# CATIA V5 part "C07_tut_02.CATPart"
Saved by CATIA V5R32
Part number: Part1
Bounding box of the stored display mesh (mm): x 0 to 32, y -32 to 32, z -15 to 36
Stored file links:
  D:\PROJECTS\Project 2022\CATIA V5 6R 2022\Resources\Tutorial Files\c07_catia_v5_6r2022_tut\C07_tut_02.CATPart
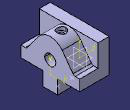
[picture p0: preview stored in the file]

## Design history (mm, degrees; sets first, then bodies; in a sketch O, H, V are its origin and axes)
Body1 (main body)
  Sketch1 on zx-plane, origin (0, 0, 0), H (-1, 0, 0), V (0, 0, 1)
    point P1 (0, 36)
    line L1 (0, 36) -> (0, 0)
    line L2 (0, 0) -> (-32, 0)
    line L3 (0, 36) -> (-12, 36)
    line L4 (-12, 36) -> (-12, 12)
    line L5 (-12, 12) -> (-32, 12)
    line L6 (-32, 12) -> (-32, 0)
    length L2 = 32
    length L3 = 12
    length L6 = 12
    distance L3 L2 = 36
    coincidence: P1 V
    vertical: L1 V, L4 V, L6 V
    horizontal: L2 H, L3 H, L5 H
  Pad1: profile Sketch1, direction (0, 1, 0), length 32, mirrored extent
  Sketch2 on face of Pad1 from Sketch1.L6, origin (32, 0, 0), H (0, 1, 0), V (0, 0, 1)
    arc A1 centre (0, 20) radius 16 from (12.9443, 29.4046) to (-12.9443, 29.4046) ccw
    point P1 (0, 20)
    reference projected line E1 (-32, 36) -> (32, 36) from edge [face of Pad1 from Sketch1.L4 | face of Pad1 from Sketch1.L3]
    line L1 (-25.5894, 12) -> (25.5894, 12)
    point P2 (-25.5894, 12)
    point P3 (25.5894, 12)
    reference projected line E2 (-32, 12) -> (32, 12) from edge [face of Pad1 from Sketch1.L6 | face of Pad1 from Sketch1.L5]
    line L2 (-25.5894, 12) -> (-12.9443, 29.4046)
    line L3 (25.5894, 12) -> (12.9443, 29.4046)
    radius A1 = 16
    angle L3 L2 = 72
    coincidence: P1 V, L1 E2
    tangency: A1 E1, L2 A1, L3 A1
    horizontal: L1 H
    symmetry: P3 P2 V
  Pad2: profile Sketch2, direction (1, 0, 0), up to the existing solid (limit type 2)
  Sketch3 on face of Pad2, origin (32, 0, 0), H (0, 1, 0), V (0, 0, 1)
    line L1 (-8, 0) -> (8, 0)
    line L2 (8, 0) -> (8, -15)
    line L3 (8, -15) -> (-8, -15)
    line L4 (-8, -15) -> (-8, 0)
    reference projected line E1 (-32, 0) -> (32, 0) from edge [face of Pad1 from Sketch1.L2 | face of Pad1 from Sketch1.L6]
    length L2 = 15
    length L3 = 16
    horizontal: L1 H, L3 H
    vertical: L2 V, L4 V
    symmetry: L2 L4 V
    coincidence: L1 E1
  Pad3: profile Sketch3, direction (1, 0, 0), up to face of Pad1 from Sketch1.L1
  Sketch4 on zx-plane, origin (0, 0, 0), H (-1, 0, 0), V (0, 0, 1)
    point P1 (-20, 36)
    reference projected line E1 (0, 36) -> (-12, 36) from edge [face of Pad1 from Sketch1.L3 | end face of Pad1]
    reference projected line E2 (0, 0) -> (0, 36) from edge [face of Pad1 from Sketch1.L1 | end face of Pad1]
    distance P1 E2 = 20
    coincidence: P1 E1
  Sketch5 on {plane type Tangent, Support face of Pad2 from Sketch2.A1, RefPoint Sketch4.P1}, origin (20, 0, 36), H (1, 0, 0), V (0, -1, 0)
    point P1 (0, 0)
    reference projected point E1 (0, 0) from Sketch4.P1
    coincidence: E1 P1
  Hole1: placed by Sketch5, at (20, 0, 36) direction (0, 0, -1), diameter 6, depth 16, V-bottom angle 120, counterbore diameter 10, counterbore depth 4
  Sketch6 on face of Pad2, origin (32, 0, 0), H (0, 1, 0), V (0, 0, 1)
    point P1 (0, 14)
    reference projected line E1 (-8, -15) -> (8, -15) from edge [face of Pad3 from Sketch3.L3 | start face of Pad3]
    distance P1 E1 = 29
    coincidence: P1 V
  Sketch7 on face of Pad2, origin (32, 0, 10), H (0, 1, 0), V (0, 0, 1)
    point P1 (0, 4)
    reference projected point E1 (0, 4) from Sketch6.P1
    coincidence: E1 P1
  Hole2: placed by Sketch7, at (32, 0, 14) direction (-1, 0, 0), diameter 12, depth 24
  Fillet1: radius 3, on edge [face of Pad1 from Sketch1.L5 | face of Pad2 from Sketch2.L3]; edge [face of Pad2 from Sketch2.L2 | face of Pad1 from Sketch1.L5]
  Sketch8 on zx-plane, origin (0, 0, 0), H (-1, 0, 0), V (0, 0, 1)
    point P1 (-24, -15)
    point P2 (-8, -15)
    reference projected line E1 (-32, -15) -> (0, -15) from edge [face of Pad3 from Sketch3.L3 | face of Pad3 from Sketch3.L2]
    reference projected line E2 (-32, -15) -> (0, -15) from edge [face of Pad3 from Sketch3.L3 | face of Pad3 from Sketch3.L2]
    reference projected line E3 (-32, -15) -> (-32, 0) from edge [face of Pad3 from Sketch3.L2 | face of Pad2]
    distance E3 P1 = 8
    distance P2 P1 = 16
    coincidence: P1 E1, P2 E2
  Sketch9 on face of Pad3 from Sketch3.L3, origin (8, 0, -15), H (1, 0, 0), V (0, -1, 0)
    point P1 (0, 0)
    reference projected point E1 (0, 0) from Sketch8.P2
    coincidence: E1 P1
  Hole3: placed by Sketch9, at (8, 0, -15) direction (0, 0, 1), diameter 6, depth 16, V-bottom angle 120, threaded, thread diameter 6.6, thread depth 10, pitch 1
  Sketch10 on face of Pad3 from Sketch3.L3, origin (24, 0, -15), H (1, 0, 0), V (0, -1, 0)
    point P1 (0, 0)
    reference projected point E1 (0, 0) from Sketch8.P1
    coincidence: E1 P1
  Hole4: placed by Sketch10, at (24, 0, -15) direction (0, 0, 1), diameter 6, depth 16, V-bottom angle 120, threaded, thread diameter 6.6, thread depth 10, pitch 1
